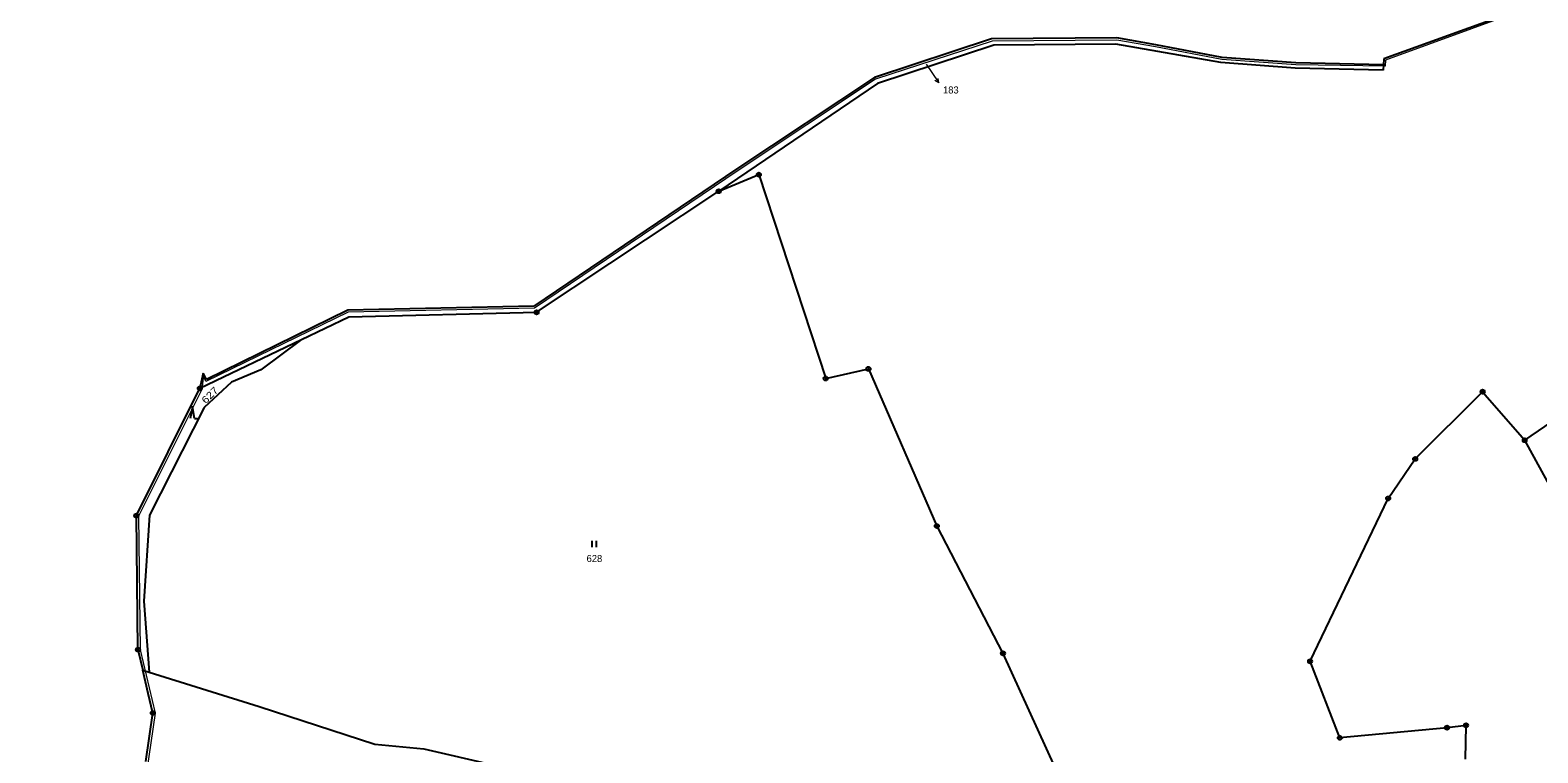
# Model space of a CAD drawing. Extents: x -653193 to -651624, y -1092017 to -1090260.
# Drawn here: x -653192 to -652826.7, y -1091036.5 to -1090861.4 of the extents above; entities that cross this region are included whole.
import ezdxf
from ezdxf.enums import TextEntityAlignment as Align

# ---------------------------------------------------------------- set-up
doc = ezdxf.new("R2010")
doc.units = 0
doc.header["$LTSCALE"] = 0.68
for name, color, linetype, lineweight in [('1', 7, 'Continuous', 25), ('3', 7, 'Continuous', 25), ('4', 7, 'Continuous', 13), ('7', 7, 'Continuous', 13), ('8', 7, 'Continuous', 25)]:
    doc.layers.add(name, color=color, linetype=linetype, lineweight=lineweight)
doc.layers.add('2', color=7, linetype='Continuous')

msp = doc.modelspace()

# ---------------------------------------------------------------- linework, layer by layer
at = {"layer": '1'}
for p, q in [((-652811.97, -1090849.49), (-652864.05, -1090868.37)), ((-652959.07, -1090863.54), (-652987.43, -1090872.86)), ((-652958.54, -1090865.03), (-652986.69, -1090874.31)), ((-652928.72, -1090863.29), (-652959.07, -1090863.54)), ((-652919.33, -1090864.96), (-652928.72, -1090863.29)), ((-652903.22, -1090868), (-652919.33, -1090864.96)), ((-652885.53, -1090870.61), (-652903.52, -1090869.22)), ((-652885.39, -1090869.28), (-652903.22, -1090868)), ((-652864.14, -1090869.81), (-652885.39, -1090869.28)), ((-652864.05, -1090868.37), (-652864.14, -1090869.81)), ((-652987.43, -1090872.86), (-653020.77, -1090895)), ((-652864.25, -1090871.12), (-652885.53, -1090870.61)), ((-652864.14, -1090869.81), (-652864.25, -1090871.12)), ((-652986.69, -1090874.31), (-653025.18, -1090900.44)), ((-653020.77, -1090895), (-653069.98, -1090928.26)), ((-653025.18, -1090900.44), (-653015.47, -1090896.41)), ((-653015.47, -1090896.41), (-652999.26, -1090945.8)), ((-653069.3, -1090929.76), (-653025.18, -1090900.44)), ((-653115.03, -1090929.26), (-653149.23, -1090946.07)), ((-653069.98, -1090928.26), (-653115.03, -1090929.26)), ((-653114.79, -1090930.83), (-653069.3, -1090929.76)), ((-652829.92, -1090960.77), (-652788.81, -1090932.56)), ((-653126.24, -1090936.33), (-653136.09, -1090943.67)), ((-653150.08, -1090944.53), (-653150.88, -1090948.18)), ((-653149.23, -1090946.07), (-653150.08, -1090944.53)), ((-653136.09, -1090943.67), (-653143.21, -1090946.7)), ((-652999.26, -1090945.8), (-652988.91, -1090943.48)), ((-652988.91, -1090943.48), (-652972.34, -1090981.57)), ((-653166.26, -1090979.02), (-653150.88, -1090948.18)), ((-653143.21, -1090946.7), (-653149.82, -1090952.82)), ((-652856.45, -1090965.29), (-652840.12, -1090949.01)), ((-652840.12, -1090949.01), (-652829.92, -1090960.77)), ((-653149.82, -1090952.82), (-653163.09, -1090978.93)), ((-652754.93, -1091097.89), (-652829.92, -1090960.77)), ((-652863, -1090974.87), (-652856.45, -1090965.29)), ((-652881.92, -1091014.33), (-652863, -1090974.87)), ((-653165.87, -1091011.49), (-653166.26, -1090979.02)), ((-653163.09, -1090978.93), (-653164.45, -1090999.77)), ((-652972.34, -1090981.57), (-652956.33, -1091012.41)), ((-653164.45, -1090999.77), (-653163.15, -1091016.93)), ((-653165.87, -1091011.49), (-653164.71, -1091016.47)), ((-652956.33, -1091012.41), (-652943.77, -1091040.03)), ((-652874.72, -1091032.87), (-652881.92, -1091014.33)), ((-653164.71, -1091016.47), (-653163.15, -1091016.93)), ((-653163.4, -1091022.1), (-653164.71, -1091016.47)), ((-653163.15, -1091016.93), (-653136.53, -1091025.29)), ((-653162.28, -1091026.88), (-653163.4, -1091022.1)), ((-653136.53, -1091025.29), (-653108.45, -1091034.44)), ((-653164, -1091038.62), (-653162.28, -1091026.88)), ((-652848.75, -1091030.42), (-652874.72, -1091032.87)), ((-652844.13, -1091029.85), (-652848.75, -1091030.42)), ((-652844.26, -1091038.01), (-652844.13, -1091029.85)), ((-653108.45, -1091034.44), (-653096.62, -1091035.52)), ((-653096.62, -1091035.52), (-653079.47, -1091039.46))]:
    msp.add_line(p, q, dxfattribs=at)
for points in [[(-652903.52, -1090869.22), (-652928.94, -1090864.83), (-652958.54, -1090865.03)], [(-653150.88, -1090948.18), (-653126.24, -1090936.33), (-653114.79, -1090930.83)]]:
    msp.add_lwpolyline(points, dxfattribs=at)
at = {"layer": '3'}
for p, q in [((-653152.175, -1090955.49), (-653151.478, -1090955.49)), ((-653055.831, -1090986.68), (-653055.831, -1090985.18)), ((-653054.83, -1090986.68), (-653054.83, -1090985.18))]:
    msp.add_line(p, q, dxfattribs=at)
msp.add_lwpolyline([(-653152.175, -1090955.49), (-653152.7, -1090952.69), (-653153.225, -1090955.49)], dxfattribs=at)
at = {"layer": '4'}
for p, q in [((-652811.48, -1090849.6), (-652863.64, -1090868.66)), ((-652958.95, -1090864.03), (-652987.21, -1090873.31)), ((-652928.75, -1090863.79), (-652958.95, -1090864.03)), ((-652919.4, -1090865.46), (-652928.75, -1090863.79)), ((-652903.31, -1090868.49), (-652919.4, -1090865.46)), ((-652885.39, -1090869.78), (-652903.31, -1090868.49)), ((-652863.64, -1090868.66), (-652863.73, -1090870.09)), ((-652987.21, -1090873.31), (-653020.5, -1090895.42)), ((-652863.73, -1090870.09), (-652885.39, -1090869.78)), ((-653020.5, -1090895.42), (-653069.84, -1090928.74)), ((-653114.95, -1090929.75), (-653149.4, -1090946.54)), ((-653069.84, -1090928.74), (-653114.95, -1090929.75)), ((-653150.02, -1090945.03), (-653150.38, -1090948.47)), ((-653149.4, -1090946.54), (-653150.02, -1090945.03))]:
    msp.add_line(p, q, dxfattribs=at)
msp.add_lwpolyline([(-653150.38, -1090948.47), (-653165.77, -1090979.18), (-653165.35, -1091011.56), (-653161.74, -1091026.92), (-653176.52, -1091128.14), (-653178.05, -1091139.13), (-653181.58, -1091166.64), (-653191.27, -1091202.57), (-653191.99, -1091279.86), (-653185.4, -1091322.52), (-653167.88, -1091342.01), (-653153.56, -1091372.39), (-653125.53, -1091427.08), (-653100.42, -1091487.61), (-653082.33, -1091581.28), (-653077.75, -1091583), (-653070.49, -1091617.25)], dxfattribs=at)
at = {"layer": '7'}
msp.add_line((-652971.852, -1090874.188), (-652971.997, -1090873.078), dxfattribs=at)
msp.add_lwpolyline([(-652974.94, -1090869.62), (-652973.53, -1090871.7), (-652971.852, -1090874.188), (-652972.827, -1090873.638)], dxfattribs=at)
at = {"layer": '8'}
for centre, radius in [((-653015.47, -1090896.4099), 0.5), ((-653015.47, -1090896.4099), 0.0303), ((-653025.18, -1090900.4399), 0.5), ((-653025.18, -1090900.4399), 0.0303), ((-653069.3, -1090929.7599), 0.5), ((-653069.3, -1090929.7599), 0.0303), ((-652999.26, -1090945.7999), 0.5), ((-652999.26, -1090945.7999), 0.0303), ((-652988.91, -1090943.4799), 0.5), ((-652988.91, -1090943.4799), 0.0303), ((-653150.88, -1090948.1799), 0.5), ((-653150.88, -1090948.1799), 0.0303), ((-652840.12, -1090949.0099), 0.5), ((-652840.12, -1090949.0099), 0.0303), ((-652829.92, -1090960.7699), 0.5), ((-652829.92, -1090960.7699), 0.0303), ((-652856.45, -1090965.2899), 0.5), ((-652856.45, -1090965.2899), 0.0303), ((-652863, -1090974.8699), 0.5), ((-652863, -1090974.8699), 0.0303), ((-653166.26, -1090979.0199), 0.5), ((-653166.26, -1090979.0199), 0.0303), ((-652972.34, -1090981.5699), 0.5), ((-652972.34, -1090981.5699), 0.0303), ((-653165.87, -1091011.4899), 0.5), ((-653165.87, -1091011.4899), 0.0303), ((-652956.33, -1091012.4099), 0.5), ((-652956.33, -1091012.4099), 0.0303), ((-652881.92, -1091014.3299), 0.5), ((-652881.92, -1091014.3299), 0.0303), ((-653162.28, -1091026.8799), 0.5), ((-653162.28, -1091026.8799), 0.0303), ((-652848.75, -1091030.4199), 0.5), ((-652848.75, -1091030.4199), 0.0303), ((-652844.13, -1091029.8499), 0.5), ((-652844.13, -1091029.8499), 0.0303), ((-652874.72, -1091032.8699), 0.5), ((-652874.72, -1091032.8699), 0.0303)]:
    msp.add_circle(centre, radius, dxfattribs=at)

# ---------------------------------------------------------------- texts
at = {"layer": '2'}
msp.add_text('183', height=1.7, dxfattribs=at).set_placement((-652970.85, -1090876.745))
at = {"layer": '2', "width": 1.2}
msp.add_text('627', height=1.7, rotation=45, dxfattribs=at).set_placement((-653147.8425, -1090950.4435), align=Align.CENTER)
at = {"layer": '2'}
msp.add_text('628', height=1.7, dxfattribs=at).set_placement((-653055.299, -1090990.275), align=Align.CENTER)

doc.saveas('drawing.dxf')
